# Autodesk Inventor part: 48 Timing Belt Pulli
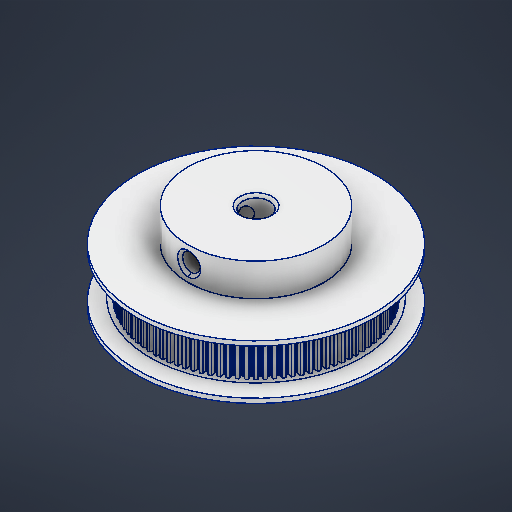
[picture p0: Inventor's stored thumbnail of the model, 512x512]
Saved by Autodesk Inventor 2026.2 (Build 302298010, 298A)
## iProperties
Created: 2026-04
Part Number: 48 Timing Belt Pulli
Material: 알루미늄 6061
Document SubType Name: Modeling
Designer: work
Density: 2.7 g/cm^3
Appearance: 알루미늄 - 평지
Author: work
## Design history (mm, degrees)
sketch "스케치1"
  geometry: C1 r 22 at (0, 0); 1 further point
  constraints: 1 centre point, 1 coincident
  dimensions: "d0" = 44 diameter of C1
extrude "돌출1" new body sketch "스케치1" distance "d1" = 10; taper "d2" = 0 deg
sketch "스케치2"
  geometry: C1 r 12.5 at (0, 0); 1 further point
  constraints: 1 centre point, 1 coincident
  dimensions: "d3" = 25 diameter of C1
extrude "돌출2" join sketch "스케치2" distance "d4" = 6; taper "d5" = 0 deg
sketch "스케치3"
  geometry: C1 r 2.5 at (0, 0); 1 further point
  constraints: 1 centre point, 1 coincident
  dimensions: "d6" = 5 diameter of C1
extrude "돌출3" cut sketch "스케치3" extent not by distance; stored distance "d7" = 0; taper "d8" = 0 deg
node "작업 평면1"
sketch "스케치4"
  geometry: L1 (0, 0)-(0, 18.7); L2 (0, 18.7)-(0.251, 18.7); L3 (0.251, 18.7)-(0.383, 17.95); L4 (0.383, 17.95)-(0.634, 17.95); L5 (0, 18.7)-(-0.251, 18.7); L6 (-0.251, 18.7)-(-0.383, 17.95); L7 (-0.383, 17.95)-(-0.634, 17.95); L8 (0, 0)-(-1.223, 18.66); L9 (-1.223, 18.66)-(-0.973, 18.676); L10 (-0.973, 18.676)-(-0.791, 17.937); L11 (-0.791, 17.937)-(-0.541, 17.953); L12 (-1.223, 18.66)-(-1.474, 18.644); L13 (-1.474, 18.644)-(-1.556, 17.886); L14 (-1.556, 17.886)-(-1.807, 17.87); L15 (0, 0)-(-2.441, 18.54); L16 (-2.441, 18.54)-(-2.192, 18.573); L17 (-2.192, 18.573)-(-1.963, 17.846); L18 (-1.963, 17.846)-(-1.714, 17.879); L19 (-2.441, 18.54)-(-2.69, 18.507); L20 (-2.69, 18.507)-(-2.723, 17.746); L21 (-2.723, 17.746)-(-2.972, 17.714); L22 (0, 0)-(-3.648, 18.341); L23 (-3.648, 18.341)-(-3.402, 18.39); L24 (-3.402, 18.39)-(-3.126, 17.68); L25 (-3.126, 17.68)-(-2.88, 17.729); L26 (-3.648, 18.341)-(-3.894, 18.292); L27 (-3.894, 18.292)-(-3.878, 17.53); L28 (-3.878, 17.53)-(-4.124, 17.481); L29 (0, 0)-(-4.84, 18.063); L30 (-4.84, 18.063)-(-4.597, 18.128); L31 (-4.597, 18.128)-(-4.276, 17.438); L32 (-4.276, 17.438)-(-4.033, 17.503); L33 (-4.84, 18.063)-(-5.082, 17.998); L34 (-5.082, 17.998)-(-5.016, 17.239); L35 (-5.016, 17.239)-(-5.259, 17.174); L36 (0, 0)-(-6.011, 17.708); L37 (-6.011, 17.708)-(-5.773, 17.788); L38 (-5.773, 17.788)-(-5.407, 17.121); L39 (-5.407, 17.121)-(-5.169, 17.201); L40 (-6.011, 17.708)-(-6.249, 17.627); L41 (-6.249, 17.627)-(-6.133, 16.874); L42 (-6.133, 16.874)-(-6.371, 16.793); L43 (0, 0)-(-7.156, 17.277); L44 (-7.156, 17.277)-(-6.924, 17.373); L45 (-6.924, 17.373)-(-6.515, 16.73); L46 (-6.515, 16.73)-(-6.283, 16.826); L47 (-7.156, 17.277)-(-7.388, 17.18); L48 (-7.388, 17.18)-(-7.223, 16.437); L49 (-7.223, 16.437)-(-7.455, 16.341); L50 (0, 0)-(-8.271, 16.772); L51 (-8.271, 16.772)-(-8.046, 16.883); L52 (-8.046, 16.883)-(-7.595, 16.268); L53 (-7.595, 16.268)-(-7.37, 16.379); L54 (-8.271, 16.772)-(-8.496, 16.66); L55 (-8.496, 16.66)-(-8.283, 15.929); L56 (-8.283, 15.929)-(-8.508, 15.818); L57 (0, 0)-(-9.35, 16.195); L58 (-9.35, 16.195)-(-9.133, 16.32); L59 (-9.133, 16.32)-(-8.643, 15.737); L60 (-8.643, 15.737)-(-8.426, 15.862); L61 (-9.35, 16.195)-(-9.567, 16.069); L62 (-9.567, 16.069)-(-9.307, 15.354); L63 (-9.307, 15.354)-(-9.524, 15.228); L64 (0, 0)-(-10.389, 15.548)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; C1 r 2.5 at (0, 0) reference; C2 r 2.5 at (0, 0) reference; C3 r 22 at (0, 0) reference; 97 further points
  constraints: 1344 end point, 3 symmetric about line, 2 coincident, 2 parallel, 1 horizontal, 1 vertical, 1439 other
  dimensions: "d10" = 18.7 distance of L1.start L1.end; "d11" = 0.63438 horizontal distance of L1.end L4.end; "d12" = 100 deg angle of L2 L3; "d13" = 0.75 vertical distance of L2.end L3.end; "d16" = 360 deg dimension on L1.start L1.end (derived)
extrude "돌출4" cut sketch "스케치4" distance "d18" = 7; taper "d19" = 0 deg
chamfer "모따기1" distance "d20" = 2.5; stored, may be unused: second distance "d21" = 2, angle "d22" = 15 deg
chamfer "모따기2" distance "d23" = 2.5; stored, may be unused: second distance "d24" = 2, angle "d25" = 15 deg
node "작업 평면2"
sketch "스케치5"
  geometry: L1 (6, -12.5)-(6, 12.5) reference; L2 (6, 0)-(0, 0); L3 (0, -22)-(0, 22) reference; 2 further points
  constraints: 3 midpoint, 2 end point, 1 horizontal
hole "구멍1" sketch "스케치5" at (3, 0) diameter "d26" = 3.242; stored, may be unused: countersink angle "d30" = 90 deg, drill point angle "d32" = 0 deg; dims "d27" = 8, "d28" = 7.2, "d29" = 4.2, "d31" = 8
chamfer "모따기3" distance "d36" = 0.5; stored, may be unused: second distance "d37" = 2, angle "d38" = 15 deg
node "솔리드1"
pattern_circular "원형 패턴1" dims angle "d34" = 360 deg
node "투영된 루프1"
node "스케치 - 원형 패턴1" dims "d16" = 360 deg (derived)
feature "A9D066F2-1C7D-4E18-AEED-F7BC21143FA4" dims "d26" = 3.242, "d27" = 8, "d28" = 7.2, "d29" = 4.2, "d30" = 90 deg, "d31" = 8, "d32" = 0
other parameters: "d9" = -1.5, "d10" = 18.7, "d11" = 0.63438, "d12" = 100 deg, "d13" = 0.75
